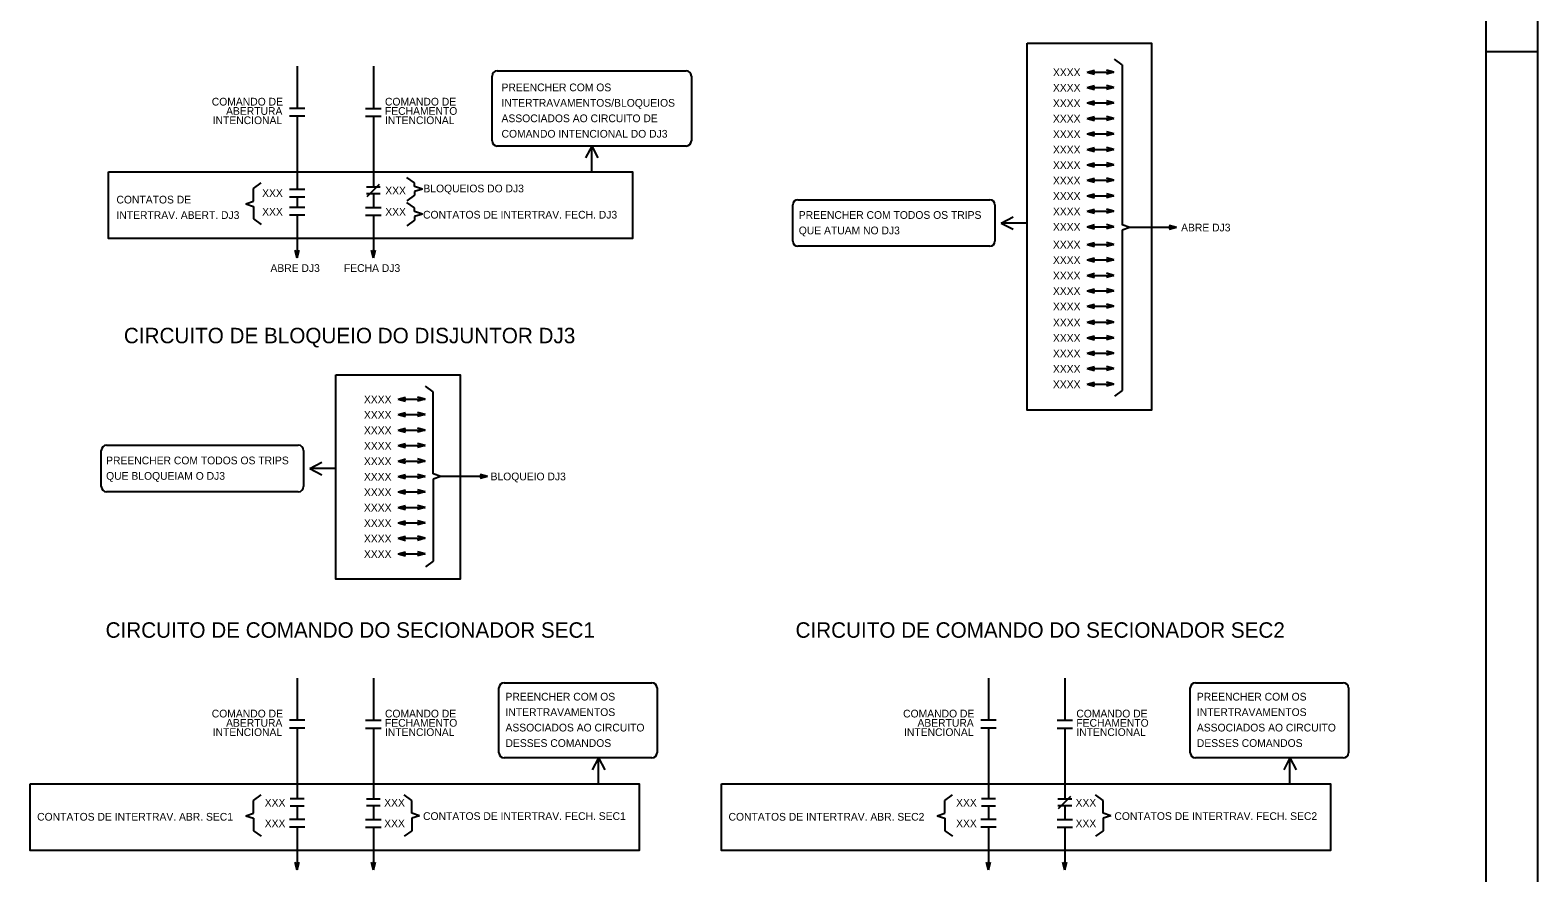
# Model space of a CAD drawing. Extents: x 400 to 1404, y 358 to 952.
# Drawn here: x 1111 to 1403.6, y 495.6 to 659.1 of the extents above; entities that cross this region are included whole.
import ezdxf

# ---------------------------------------------------------------- set-up
doc = ezdxf.new("R2010")
doc.units = 0
doc.layers.add('New Level (0)', color=7, linetype='Continuous')

# ---------------------------------------------------------------- blocks, each defined once
blk = doc.blocks.new('39')
for p, q in [((0, 0), (1.45, 0.39)), ((0, 0), (5.22, 0)), ((0, 0), (1.45, -0.39)), ((5.22, 0), (3.77, 0.39)), ((5.22, 0), (3.77, -0.39))]:
    blk.add_line(p, q)

msp = doc.modelspace()

# ---------------------------------------------------------------- linework, layer by layer
for p, q in [((1322.92, 652.37), (1321.42, 653.45)), ((1162.82, 652.07), (1162.82, 643.9)), ((1177.61, 652.07), (1177.61, 643.9)), ((1316.1, 650.95), (1317.55, 651.34)), ((1316.1, 650.95), (1321.32, 650.95)), ((1316.1, 650.95), (1317.55, 650.56)), ((1321.32, 650.95), (1319.87, 651.34)), ((1321.32, 650.95), (1319.87, 650.56)), ((1322.92, 652.37), (1322.92, 621.28)), ((1316.1, 647.95), (1317.55, 648.34)), ((1316.1, 647.95), (1321.32, 647.95)), ((1316.1, 647.95), (1317.55, 647.56)), ((1321.32, 647.95), (1319.87, 648.34)), ((1321.32, 647.95), (1319.87, 647.56)), ((1164.32, 643.9), (1161.32, 643.9)), ((1176.11, 643.9), (1179.11, 643.9)), ((1316.1, 644.95), (1317.55, 645.34)), ((1316.1, 644.95), (1321.32, 644.95)), ((1316.1, 644.95), (1317.55, 644.56)), ((1321.32, 644.95), (1319.87, 645.34)), ((1321.32, 644.95), (1319.87, 644.56)), ((1164.32, 642.4), (1161.32, 642.4)), ((1162.82, 642.4), (1162.82, 628.16)), ((1176.11, 642.4), (1179.11, 642.4)), ((1177.61, 642.4), (1177.61, 628.66)), ((1154.36, 628.35), (1155.86, 629.43)), ((1176.42, 626.79), (1178.8, 629.18)), ((1185.62, 629.44), (1184.12, 630.52)), ((1185.62, 628.75), (1185.62, 629.44)), ((1154.36, 625.88), (1154.36, 628.35)), ((1164.32, 628.16), (1161.32, 628.16)), ((1164.32, 626.66), (1161.32, 626.66)), ((1162.82, 626.66), (1162.82, 624.66)), ((1176.26, 628.66), (1178.96, 628.66)), ((1178.96, 627.31), (1176.26, 627.31)), ((1177.61, 627.16), (1177.61, 624.66)), ((1185.62, 627.07), (1184.12, 625.99)), ((1187.12, 628.25), (1185.62, 628.75)), ((1187.12, 628.25), (1185.62, 627.75)), ((1185.62, 627.75), (1185.62, 627.07)), ((1152.86, 625.38), (1154.36, 625.88)), ((1152.86, 625.38), (1154.36, 624.88)), ((1154.36, 624.88), (1154.36, 622.48)), ((1164.32, 624.66), (1161.32, 624.66)), ((1176.11, 624.66), (1179.11, 624.66)), ((1176.11, 624.66), (1179.11, 624.66)), ((1185.62, 624.58), (1184.12, 625.67)), ((1185.62, 623.9), (1185.62, 624.58)), ((1187.12, 623.4), (1185.62, 623.9)), ((1187.12, 623.4), (1185.62, 622.9)), ((1154.36, 622.48), (1155.86, 621.4)), ((1164.32, 623.16), (1161.32, 623.16)), ((1162.82, 623.16), (1162.82, 614.92)), ((1176.11, 623.16), (1179.11, 623.16)), ((1176.11, 623.16), (1179.11, 623.16)), ((1177.61, 623.16), (1177.61, 614.92)), ((1185.62, 622.22), (1184.12, 621.13)), ((1185.62, 622.9), (1185.62, 622.22)), ((1324.42, 620.78), (1322.92, 621.28)), ((1324.42, 620.78), (1322.92, 620.28)), ((1322.92, 620.28), (1322.92, 589.18)), ((1333.48, 620.78), (1324.42, 620.78)), ((1333.48, 620.78), (1332.03, 621.16)), ((1333.48, 620.78), (1332.03, 620.39)), ((1316.1, 617.51), (1317.55, 617.9)), ((1316.1, 617.51), (1321.32, 617.51)), ((1316.1, 617.51), (1317.55, 617.12)), ((1321.32, 617.51), (1319.87, 617.9)), ((1321.32, 617.51), (1319.87, 617.12)), ((1162.82, 614.92), (1162.43, 616.37)), ((1162.82, 614.92), (1163.21, 616.37)), ((1177.61, 614.92), (1177.22, 616.37)), ((1177.61, 614.92), (1178, 616.37)), ((1316.1, 602.41), (1317.55, 602.8)), ((1321.32, 602.41), (1319.87, 602.8)), ((1316.1, 602.41), (1321.32, 602.41)), ((1316.1, 602.41), (1317.55, 602.02)), ((1321.32, 602.41), (1319.87, 602.02)), ((1189.23, 588.91), (1187.73, 589.99)), ((1189.23, 572.99), (1189.23, 588.91)), ((1322.92, 589.18), (1321.42, 588.1)), ((1182.41, 587.49), (1183.86, 587.88)), ((1182.41, 587.49), (1187.63, 587.49)), ((1182.41, 587.49), (1183.86, 587.1)), ((1187.63, 587.49), (1186.18, 587.88)), ((1187.63, 587.49), (1186.18, 587.1)), ((1182.41, 581.49), (1183.86, 581.88)), ((1182.41, 581.49), (1187.63, 581.49)), ((1182.41, 581.49), (1183.86, 581.1)), ((1187.63, 581.49), (1186.18, 581.88)), ((1187.63, 581.49), (1186.18, 581.1)), ((1190.73, 572.49), (1189.23, 572.99)), ((1190.73, 572.49), (1189.23, 571.99)), ((1189.23, 571.99), (1189.23, 556.07)), ((1199.79, 572.49), (1190.73, 572.49)), ((1199.79, 572.49), (1198.34, 572.88)), ((1199.79, 572.49), (1198.34, 572.1)), ((1189.23, 556.07), (1187.73, 554.99)), ((1162.82, 533.36), (1162.82, 525.19)), ((1177.61, 533.36), (1177.61, 525.19)), ((1296.98, 533.36), (1296.98, 525.19)), ((1311.77, 533.36), (1311.77, 525.19)), ((1164.32, 525.19), (1161.32, 525.19)), ((1176.11, 525.19), (1179.11, 525.19)), ((1298.48, 525.19), (1295.48, 525.19)), ((1310.27, 525.19), (1313.27, 525.19)), ((1164.32, 523.69), (1161.32, 523.69)), ((1162.82, 523.69), (1162.82, 509.95)), ((1176.11, 523.69), (1179.11, 523.69)), ((1177.61, 523.69), (1177.61, 509.95)), ((1298.48, 523.69), (1295.48, 523.69)), ((1296.98, 523.69), (1296.98, 509.95)), ((1310.27, 523.69), (1313.27, 523.69)), ((1311.77, 523.69), (1311.77, 509.95)), ((1154.36, 509.63), (1155.86, 510.71)), ((1154.36, 507.17), (1154.36, 509.63)), ((1164.17, 509.95), (1161.47, 509.95)), ((1176.26, 509.95), (1178.96, 509.95)), ((1185.08, 509.63), (1183.58, 510.71)), ((1185.08, 507.17), (1185.08, 509.63)), ((1288.52, 509.63), (1290.02, 510.71)), ((1288.52, 507.17), (1288.52, 509.63)), ((1298.33, 509.95), (1295.63, 509.95)), ((1310.42, 509.95), (1313.12, 509.95)), ((1310.58, 508.08), (1312.97, 510.47)), ((1319.24, 509.63), (1317.74, 510.71)), ((1319.24, 507.17), (1319.24, 509.63)), ((1152.86, 506.67), (1154.36, 507.17)), ((1152.86, 506.67), (1154.36, 506.17)), ((1154.36, 506.17), (1154.36, 503.76)), ((1161.47, 508.6), (1164.17, 508.6)), ((1162.82, 508.45), (1162.82, 505.94)), ((1178.96, 508.6), (1176.26, 508.6)), ((1177.61, 508.45), (1177.61, 505.94)), ((1186.58, 506.67), (1185.08, 507.17)), ((1186.58, 506.67), (1185.08, 506.17)), ((1185.08, 506.17), (1185.08, 503.76)), ((1287.02, 506.67), (1288.52, 507.17)), ((1287.02, 506.67), (1288.52, 506.17)), ((1288.52, 506.17), (1288.52, 503.76)), ((1295.63, 508.6), (1298.33, 508.6)), ((1296.98, 508.45), (1296.98, 505.94)), ((1313.12, 508.6), (1310.42, 508.6)), ((1311.77, 508.45), (1311.77, 505.94)), ((1320.74, 506.67), (1319.24, 507.17)), ((1320.74, 506.67), (1319.24, 506.17)), ((1319.24, 506.17), (1319.24, 503.76)), ((1154.36, 503.76), (1155.86, 502.68)), ((1164.32, 505.94), (1161.32, 505.94)), ((1164.32, 504.44), (1161.32, 504.44)), ((1162.82, 504.44), (1162.82, 496.21)), ((1176.11, 505.94), (1179.11, 505.94)), ((1176.11, 504.44), (1179.11, 504.44)), ((1177.61, 504.44), (1177.61, 496.21)), ((1185.08, 503.76), (1183.58, 502.68)), ((1288.52, 503.76), (1290.02, 502.68)), ((1298.48, 505.94), (1295.48, 505.94)), ((1298.48, 504.44), (1295.48, 504.44)), ((1296.98, 504.44), (1296.98, 496.21)), ((1310.27, 505.94), (1313.27, 505.94)), ((1310.27, 504.44), (1313.27, 504.44)), ((1311.77, 504.44), (1311.77, 496.21)), ((1319.24, 503.76), (1317.74, 502.68)), ((1162.82, 496.21), (1162.43, 497.66)), ((1162.82, 496.21), (1163.21, 497.66)), ((1177.61, 496.21), (1177.22, 497.66)), ((1177.61, 496.21), (1178, 497.66)), ((1296.98, 496.21), (1296.59, 497.66)), ((1296.98, 496.21), (1297.37, 497.66)), ((1311.77, 496.21), (1311.38, 497.66)), ((1311.77, 496.21), (1312.16, 497.66))]:
    msp.add_line(p, q)
at = {"layer": 'New Level (0)'}
for p, q in [((1403.58, 357.96), (1403.58, 951.96)), ((1403.58, 357.96), (1403.58, 951.96)), ((1393.58, 367.96), (1393.58, 941.96)), ((1393.58, 367.96), (1393.58, 941.96)), ((1393.58, 654.96), (1403.58, 654.96)), ((1200.66, 637.59), (1200.66, 650.18)), ((1201.66, 651.18), (1238.32, 651.18)), ((1239.32, 650.18), (1239.32, 637.59)), ((1238.32, 636.59), (1201.66, 636.59)), ((1219.99, 636.59), (1218.78, 634.29)), ((1219.99, 631.56), (1219.99, 636.59)), ((1219.99, 636.59), (1221.2, 634.29)), ((1259.99, 626.17), (1267.34, 626.17)), ((1267.34, 626.17), (1297.21, 626.17)), ((1258.99, 618.14), (1258.99, 625.17)), ((1298.21, 625.17), (1298.21, 618.14)), ((1299.45, 621.65), (1301.75, 622.86)), ((1304.48, 621.65), (1299.45, 621.65)), ((1299.45, 621.65), (1301.75, 620.45)), ((1297.21, 617.14), (1259.99, 617.14)), ((1124.82, 570.52), (1124.82, 577.55)), ((1125.82, 578.55), (1133.17, 578.55)), ((1133.17, 578.55), (1163.05, 578.55)), ((1164.05, 577.55), (1164.05, 570.52)), ((1165.29, 574.03), (1167.58, 575.24)), ((1170.32, 574.03), (1165.29, 574.03)), ((1165.29, 574.03), (1167.58, 572.82)), ((1163.05, 569.52), (1125.82, 569.52)), ((1201.98, 518.88), (1201.98, 531.46)), ((1202.98, 532.46), (1231.66, 532.46)), ((1232.66, 531.46), (1232.66, 518.88)), ((1336.14, 518.88), (1336.14, 531.46)), ((1337.14, 532.46), (1365.82, 532.46)), ((1366.82, 531.46), (1366.82, 518.88)), ((1231.66, 517.88), (1202.98, 517.88)), ((1221.31, 517.88), (1220.1, 515.58)), ((1221.31, 512.85), (1221.31, 517.88)), ((1221.31, 517.88), (1222.52, 515.58)), ((1365.82, 517.88), (1337.14, 517.88)), ((1355.47, 517.88), (1354.26, 515.58)), ((1355.47, 512.85), (1355.47, 517.88)), ((1355.47, 517.88), (1356.68, 515.58))]:
    msp.add_line(p, q, dxfattribs=at)
for points in [[(1304.48, 656.57), (1328.61, 656.57), (1328.61, 585.33), (1304.48, 585.33)], [(1126.19, 631.56), (1227.89, 631.56), (1227.89, 618.67), (1126.19, 618.67)], [(1170.32, 592.18), (1194.45, 592.18), (1194.45, 552.54), (1170.32, 552.54)], [(1111.01, 512.85), (1229.2, 512.85), (1229.2, 499.96), (1111.01, 499.96)], [(1245.17, 512.85), (1363.37, 512.85), (1363.37, 499.96), (1245.17, 499.96)]]:
    msp.add_lwpolyline(points, close=True, dxfattribs=at)
for centre, start, end in [((1201.66, 650.18), 90, 180), ((1238.32, 650.18), 0, 90), ((1201.66, 637.59), 180, 270), ((1238.32, 637.59), 270, 0), ((1259.99, 625.17), 90, 180), ((1297.21, 625.17), 0, 90), ((1259.99, 618.14), 180, 270), ((1297.21, 618.14), 270, 0), ((1125.82, 577.55), 90, 180), ((1163.05, 577.55), 0, 90), ((1125.82, 570.52), 180, 270), ((1163.05, 570.52), 270, 0), ((1202.98, 531.46), 90, 180), ((1231.66, 531.46), 0, 90), ((1337.14, 531.46), 90, 180), ((1365.82, 531.46), 0, 90), ((1202.98, 518.88), 180, 270), ((1231.66, 518.88), 270, 0), ((1337.14, 518.88), 180, 270), ((1365.82, 518.88), 270, 0)]:
    msp.add_arc(centre, 1, start, end, dxfattribs=at)

# ---------------------------------------------------------------- block references
for p in [(1316.1, 641.95), (1316.1, 638.95), (1316.1, 635.95), (1316.1, 632.95), (1316.1, 629.95), (1316.1, 626.95), (1316.1, 623.95), (1316.1, 620.95), (1316.1, 614.51), (1316.1, 611.51), (1316.1, 608.51), (1316.1, 605.51), (1316.1, 599.41), (1316.1, 596.41), (1316.1, 593.41), (1316.1, 590.41), (1182.41, 584.49), (1182.41, 578.49), (1182.41, 575.49), (1182.41, 572.49), (1182.41, 569.49), (1182.41, 566.49), (1182.41, 563.49), (1182.41, 560.49), (1182.41, 557.49)]:
    msp.add_blockref('39', p)

# ---------------------------------------------------------------- texts
for s, height, p in [('XXXX', 1.5, (1309.48, 650.15)), ('PREENCHER COM OS ', 1.5, (1202.48, 647.22)), ('XXXX', 1.5, (1309.48, 647.15)), ('COMANDO DE', 1.5, (1146.25, 644.45)), (' ABERTURA', 1.5, (1148.47, 642.65)), ('COMANDO DE ', 1.5, (1179.86, 644.45)), ('FECHAMENTO ', 1.5, (1179.86, 642.65)), ('INTERTRAVAMENTOS/BLOQUEIOS', 1.5, (1202.48, 644.22)), ('XXXX', 1.5, (1309.48, 644.15)), (' INTENCIONAL', 1.5, (1145.87, 640.85)), ('INTENCIONAL', 1.5, (1179.86, 640.85)), ('ASSOCIADOS AO CIRCUITO DE ', 1.5, (1202.48, 641.22)), ('XXXX', 1.5, (1309.48, 641.15)), ('COMANDO INTENCIONAL DO DJ3', 1.5, (1202.48, 638.22)), ('XXXX', 1.5, (1309.48, 638.15)), ('XXXX', 1.5, (1309.48, 635.15)), ('XXXX', 1.5, (1309.48, 632.15)), ('BLOQUEIOS DO DJ3', 1.5, (1187.32, 627.61)), ('XXXX', 1.5, (1309.48, 629.15)), ('CONTATOS DE ', 1.5, (1127.76, 625.45)), ('XXX', 1.5, (1156.03, 626.72)), ('XXX', 1.5, (1179.92, 627.21)), ('XXXX', 1.5, (1309.48, 626.15)), ('INTERTRAV. ABERT. DJ3', 1.5, (1127.76, 622.45)), ('XXX', 1.5, (1156.03, 623.09)), ('XXX', 1.5, (1179.92, 623.09)), ('CONTATOS DE INTERTRAV. FECH. DJ3', 1.5, (1187.25, 622.52)), ('PREENCHER COM TODOS OS TRIPS', 1.5, (1260.16, 622.47)), ('XXXX', 1.5, (1309.48, 623.15)), ('QUE ATUAM NO DJ3', 1.5, (1260.16, 619.47)), ('XXXX', 1.5, (1309.48, 620.15)), ('ABRE DJ3', 1.5, (1334.35, 620.03)), ('XXXX', 1.5, (1309.48, 616.71)), ('XXXX', 1.5, (1309.48, 613.71)), ('ABRE DJ3', 1.5, (1157.64, 612.17)), ('FECHA DJ3', 1.5, (1171.9, 612.17)), ('XXXX', 1.5, (1309.48, 610.71)), ('XXXX', 1.5, (1309.48, 607.71)), ('XXXX', 1.5, (1309.48, 604.71)), ('XXXX', 1.5, (1309.48, 601.61)), ('CIRCUITO DE BLOQUEIO DO DISJUNTOR DJ3', 3, (1129.2, 598.33)), ('XXXX', 1.5, (1309.48, 598.61)), ('XXXX', 1.5, (1309.48, 595.61)), ('XXXX', 1.5, (1309.48, 592.61)), ('XXXX', 1.5, (1309.48, 589.61)), ('XXXX', 1.5, (1175.78, 586.69)), ('XXXX', 1.5, (1175.78, 583.69)), ('XXXX', 1.5, (1175.78, 580.69)), ('PREENCHER COM TODOS OS TRIPS', 1.5, (1125.75, 574.85)), ('XXXX', 1.5, (1175.78, 577.69)), ('XXXX', 1.5, (1175.78, 574.69)), ('QUE BLOQUEIAM O DJ3', 1.5, (1125.75, 571.85)), ('XXXX', 1.5, (1175.78, 571.69)), ('BLOQUEIO DJ3', 1.5, (1200.36, 571.74)), ('XXXX', 1.5, (1175.78, 568.69)), ('XXXX', 1.5, (1175.78, 565.69)), ('XXXX', 1.5, (1175.78, 562.69)), ('XXXX', 1.5, (1175.78, 559.69)), ('XXXX', 1.5, (1175.78, 556.69)), ('CIRCUITO DE COMANDO DO SECIONADOR SEC1', 3, (1125.65, 541.2)), ('CIRCUITO DE COMANDO DO SECIONADOR SEC2', 3, (1259.53, 541.2)), ('PREENCHER COM OS ', 1.5, (1203.25, 529.02)), ('PREENCHER COM OS ', 1.5, (1337.41, 529.02)), ('COMANDO DE', 1.5, (1146.25, 525.74)), ('COMANDO DE ', 1.5, (1179.86, 525.74)), ('INTERTRAVAMENTOS', 1.5, (1203.25, 526.02)), ('COMANDO DE', 1.5, (1280.41, 525.74)), ('COMANDO DE ', 1.5, (1314.02, 525.74)), ('INTERTRAVAMENTOS', 1.5, (1337.41, 526.02)), (' ABERTURA', 1.5, (1148.47, 523.94)), ('FECHAMENTO ', 1.5, (1179.86, 523.94)), ('ASSOCIADOS AO CIRCUITO ', 1.5, (1203.25, 523.02)), (' ABERTURA', 1.5, (1282.63, 523.94)), ('FECHAMENTO ', 1.5, (1314.02, 523.94)), ('ASSOCIADOS AO CIRCUITO ', 1.5, (1337.41, 523.02)), (' INTENCIONAL', 1.5, (1145.87, 522.14)), ('INTENCIONAL', 1.5, (1179.86, 522.14)), ('DESSES COMANDOS', 1.5, (1203.25, 520.02)), (' INTENCIONAL', 1.5, (1280.03, 522.14)), ('INTENCIONAL', 1.5, (1314.02, 522.14)), ('DESSES COMANDOS', 1.5, (1337.41, 520.02)), ('XXX', 1.5, (1156.53, 508.45)), ('XXX', 1.5, (1179.71, 508.45)), ('XXX', 1.5, (1290.69, 508.45)), ('XXX', 1.5, (1313.87, 508.45)), ('CONTATOS DE INTERTRAV. ABR. SEC1', 1.5, (1112.37, 505.72)), ('CONTATOS DE INTERTRAV. FECH. SEC1', 1.5, (1187.25, 505.85)), ('CONTATOS DE INTERTRAV. ABR. SEC2', 1.5, (1246.53, 505.72)), ('CONTATOS DE INTERTRAV. FECH. SEC2', 1.5, (1321.41, 505.85)), ('XXX', 1.5, (1156.53, 504.44)), ('XXX', 1.5, (1179.71, 504.44)), ('XXX', 1.5, (1290.69, 504.44)), ('XXX', 1.5, (1313.87, 504.44))]:
    msp.add_text(s, height=height).set_placement(p)

doc.saveas('drawing.dxf')
